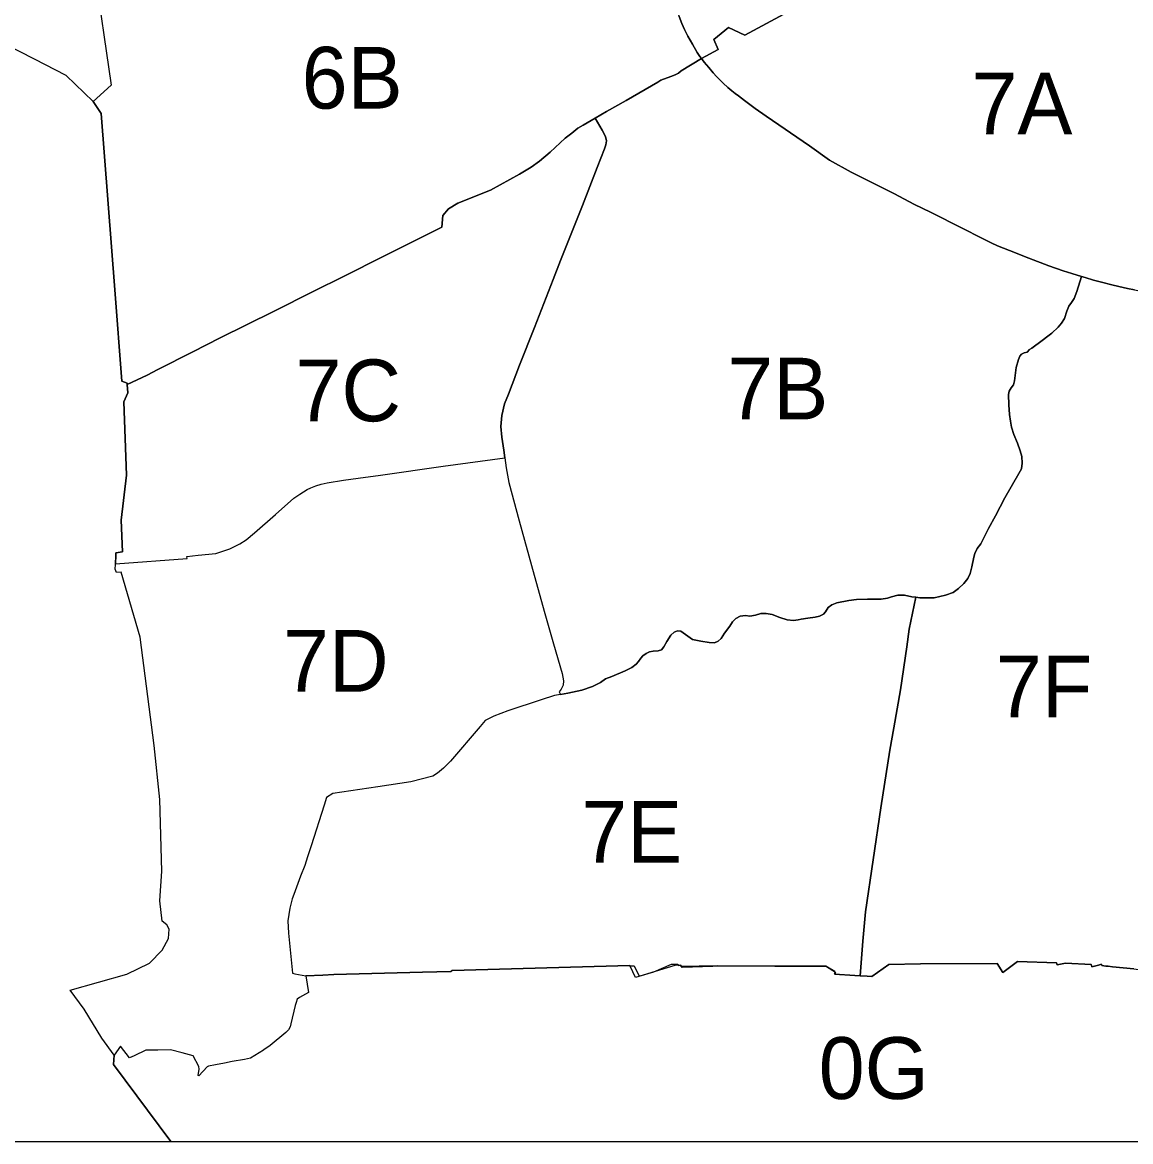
# Model space of a CAD drawing. Extents: x 152750 to 166250, y 378996 to 390000.
# Drawn here: x 157492 to 161080, y 379000 to 382624 of the extents above; entities that cross this region are included whole.
import ezdxf

# ---------------------------------------------------------------- set-up
doc = ezdxf.new("R2010")
doc.units = 0
doc.layers.add('BLT_Nummers', color=7, linetype='Continuous')
doc.layers.add('BLT_Shapes', color=7, linetype='Continuous')

msp = doc.modelspace()

# ---------------------------------------------------------------- linework, layer by layer
at = {"layer": 'BLT_Shapes'}
for p, q in [((159744.6, 382535.7), (159690.4, 382506.6)), ((159699.3, 382494.7), (159690.4, 382506.6)), ((159713.8, 382477.3), (159699.3, 382494.7)), ((159788.2, 382402.2), (159776.1, 382412.9)), ((159446.1, 382371), (159383.3, 382335)), ((159899.6, 382319.8), (159864.8, 382344.6)), ((159346.2, 382313.4), (159306.9, 382290.6)), ((159383.3, 382335), (159346.2, 382313.4)), ((159369, 382274.7), (159346.2, 382313.4)), ((160040.5, 382224.5), (159899.6, 382319.8)), ((159380.8, 382227.4), (159382.7, 382240.5)), ((159376.2, 382214.1), (159380.8, 382227.4)), ((160104.8, 382177.8), (160040.5, 382224.5)), ((160175.3, 382138.8), (160104.8, 382177.8)), ((160433.7, 382008.5), (160377.9, 382035.1)), ((160534, 381957.7), (160433.7, 382008.5)), ((158662.5, 381866.5), (158531.1, 381800.9)), ((160815.5, 381835.3), (160749.9, 381859.9)), ((160861.6, 381819.4), (160815.5, 381835.3)), ((158531.1, 381800.9), (158435.1, 381753.2)), ((160890, 381810.2), (160861.6, 381819.4)), ((160920.5, 381800.8), (160890, 381810.2)), ((160932.2, 381797.2), (160920.5, 381800.8)), ((161019.2, 381774.2), (160985.8, 381782.4)), ((159101.7, 381513.5), (159149.6, 381635.4)), ((160845, 381636.9), (160825.1, 381617.6)), ((160759.6, 381568.6), (160752.4, 381564.6)), ((159065.6, 381420.2), (159101.7, 381513.5)), ((160709.8, 381506.7), (160703.6, 381462.7)), ((157895.5, 381482), (157831.5, 381450.8)), ((157930.6, 381499.9), (157895.5, 381482)), ((157831.5, 381450.8), (157833.6, 381424.4)), ((160692.9, 381440), (160686.3, 381429.2)), ((160700.3, 381450.7), (160692.9, 381440)), ((160703.6, 381462.7), (160700.3, 381450.7)), ((157833.6, 381424.4), (157833.6, 381424.4)), ((159053.2, 381388.8), (159065.6, 381420.2)), ((160686.3, 381429.2), (160684.3, 381419.2)), ((160684.3, 381419.2), (160685.7, 381385.4)), ((160685.7, 381385.4), (160687.9, 381353.7)), ((160687.9, 381353.7), (160691.1, 381332.4)), ((160691.1, 381332.4), (160694.7, 381312.9)), ((159044.3, 381281), (159041.1, 381315.8)), ((159050.5, 381239), (159044.3, 381281)), ((159054, 381214.1), (159050.5, 381239)), ((160728.3, 381196.6), (160726.4, 381178.6)), ((160672.2, 381084.3), (160642.9, 381025.7)), ((157812.1, 381011.9), (157815.5, 380909)), ((160642.9, 381025.7), (160620.1, 380985.5)), ((160620.1, 380985.5), (160595.2, 380935.3)), ((160595.2, 380935.3), (160583.4, 380920.3)), ((157794.1, 380898.4), (157793, 380870.3)), ((157794.4, 380906), (157794.1, 380898.4)), ((157815.5, 380909), (157794.4, 380906)), ((160559.9, 380839.3), (160552.4, 380822.9)), ((160129.2, 380744.7), (160112.5, 380738.3)), ((160167.3, 380752), (160129.2, 380744.7)), ((160192.2, 380755.7), (160167.3, 380752)), ((160227.9, 380756.3), (160192.2, 380755.7)), ((160347.4, 380769.7), (160326.4, 380769.4)), ((160384.2, 380762.3), (160362.6, 380659)), ((160112.5, 380738.3), (160101.1, 380729.5)), ((159988.6, 380687.1), (159967.5, 380689.4)), ((159782, 380669.2), (159765.5, 380646.1)), ((159688.8, 380620.1), (159661.5, 380625.7)), ((159745, 380620.1), (159732.7, 380614.9)), ((159501, 380572.4), (159494.2, 380564.9)), ((159379.2, 380497.9), (159363.3, 380486.5)), ((159400, 380506.4), (159379.2, 380497.9)), ((159443.2, 380524.3), (159400, 380506.4)), ((160334.7, 380462.3), (160313.7, 380339.8)), ((159171.6, 380430.6), (159063.1, 380394.2)), ((159214.8, 380444.6), (159171.6, 380430.6)), ((159233.8, 380447.9), (159214.8, 380444.6)), ((159257.7, 380452.1), (159233.8, 380447.9)), ((159063.1, 380394.2), (159018.6, 380378)), ((160313.7, 380339.8), (160300.7, 380267.6)), ((160300.7, 380267.6), (160270.8, 380080.7)), ((158855.5, 380208.6), (158835.7, 380193)), ((158835.7, 380193), (158821.1, 380183.6)), ((158476.7, 380113.7), (158468.3, 380089.2)), ((158468.3, 380089.2), (158426.7, 379957.5)), ((160270.8, 380080.7), (160221.1, 379743.7)), ((160221.1, 379743.7), (160213.3, 379649.5)), ((160213.3, 379649.5), (160203.7, 379537.2)), ((158500, 379540.8), (158787.5, 379548.7)), ((158787.5, 379548.7), (158880.2, 379551.3)), ((159459.3, 379569.2), (159472.9, 379569.5)), ((159472.9, 379569.5), (159489, 379535.4)), ((159489, 379535.4), (159535.9, 379549.7)), ((160842.2, 379572.9), (160868.9, 379577.9)), ((160868.9, 379577.9), (160952.1, 379573.7)), ((160952.1, 379573.7), (160953.1, 379570.5)), ((160976.2, 379571.8), (160985.4, 379574.2)), ((161000.1, 379568.5), (161007.7, 379567.7)), ((161007.7, 379567.7), (161021.4, 379566.4)), ((158366, 379544.9), (158374.3, 379543.4)), ((158374.3, 379543.4), (158409.5, 379536.4)), ((160187.3, 379538.2), (160203.7, 379537.2)), ((160203.7, 379537.2), (160227.1, 379535.8))]:
    msp.add_line(p, q, dxfattribs=at)
for points in [[(157397.8, 383816.1), (157498.7, 383699.6), (157732.8, 383426.7), (157723.2, 383349.5), (157718.2, 383307.9), (157711.3, 383246), (157707.4, 383216.4), (157703.2, 383174.8), (157700.5, 383141.4), (157697.9, 383099.2), (157697.9, 383065.1), (157701.5, 382982.9), (157724.5, 382799.2), (157778.7, 382420.6), (157721.2, 382367.1), (157633.4, 382451.6), (157531.2, 382505), (157333.5, 382604.9)], [(157697.9, 383065.1), (157701.5, 382982.9), (157724.5, 382799.2), (157778.7, 382420.6), (157721.2, 382367.1)], [(159504.8, 382992), (159511, 382972.8), (159520.3, 382945.8), (159529.5, 382917.4), (159541.6, 382879), (159556.6, 382830.2), (159582.3, 382750.4), (159608.9, 382667.3), (159611, 382662.3), (159617.8, 382642.5), (159626.4, 382620.6), (159635.5, 382601.1), (159646.7, 382578.7), (159661.8, 382553.5), (159676.3, 382526.1), (159685.1, 382513.6), (159690.4, 382506.6)], [(160148.5, 382759.2), (160117.8, 382735.9), (160092.3, 382722), (159998.9, 382672.5), (159830.6, 382582), (159778.4, 382606.8), (159730.6, 382568.3), (159744.6, 382535.7)], [(159690.4, 382506.6), (159744.6, 382535.7), (159730.6, 382568.3), (159778.4, 382606.8), (159830.6, 382582), (159998.9, 382672.5)], [(159635.5, 382601.1), (159626.4, 382620.6), (159617.8, 382642.5)], [(155717.7, 379000), (157972.7, 379000), (157787.3, 379250.2), (157788.7, 379279.4), (157749, 379335.4), (157691.9, 379428.3), (157646.2, 379490.7), (157830.3, 379542), (157903.5, 379577.9), (157944.1, 379620.1), (157965.1, 379658), (157967.3, 379687.8), (157959.6, 379702), (157944.4, 379713.7), (157937.2, 379779.1), (157943.6, 379875.6), (157936.4, 380107.4), (157918.8, 380283), (157872.7, 380633.2), (157811.6, 380843.6), (157796.6, 380842.1), (157792.4, 380853.5), (157793, 380868), (157794.1, 380898.4), (157794.4, 380906), (157815.5, 380909), (157812.1, 381011.9), (157828.6, 381158), (157820.6, 381395.1), (157833.6, 381424.4), (157831.5, 381450.8), (157831.1, 381455.5), (157813.9, 381461.8), (157791.1, 381758.1), (157746.8, 382329.2), (157721.2, 382367.1), (157633.4, 382451.6), (157531.2, 382505), (157333.5, 382604.9)], [(159676.3, 382526.1), (159661.8, 382553.5), (159646.7, 382578.7), (159635.5, 382601.1)], [(159690.4, 382506.6), (159685.1, 382513.6), (159676.3, 382526.1)], [(159346.2, 382313.4), (159383.3, 382335), (159446.1, 382371), (159548.6, 382430.3), (159559.2, 382436.5), (159591.1, 382448.3), (159605.5, 382454.2), (159615.9, 382459.3), (159624.4, 382466.4), (159690.4, 382506.6)], [(159690.4, 382506.6), (159624.4, 382466.4), (159615.9, 382459.3), (159605.5, 382454.2)], [(159690.4, 382506.6), (159699.3, 382494.7), (159713.8, 382477.3), (159728.3, 382460.4), (159739.5, 382448), (159748.4, 382438.3), (159760.8, 382427), (159776.1, 382412.9), (159788.2, 382402.2), (159799.8, 382393.1), (159810.1, 382385.4), (159829.9, 382370.3), (159864.8, 382344.6), (159899.6, 382319.8), (160040.5, 382224.5), (160104.8, 382177.8), (160175.3, 382138.8), (160314.9, 382068.2), (160377.9, 382035.1), (160433.7, 382008.5), (160534, 381957.7), (160598.4, 381924.9), (160628.2, 381910.4), (160648.6, 381900.4), (160687.6, 381885.3), (160749.9, 381859.9), (160815.5, 381835.3), (160861.6, 381819.4), (160890, 381810.2), (160920.5, 381800.8)], [(159605.5, 382454.2), (159591.1, 382448.3), (159559.2, 382436.5)], [(159776.1, 382412.9), (159760.8, 382427), (159748.4, 382438.3), (159739.5, 382448), (159728.3, 382460.4), (159713.8, 382477.3)], [(159559.2, 382436.5), (159548.6, 382430.3), (159446.1, 382371)], [(159810.1, 382385.4), (159799.8, 382393.1), (159788.2, 382402.2)], [(159864.8, 382344.6), (159829.9, 382370.3), (159810.1, 382385.4)], [(157721.2, 382367.1), (157746.8, 382329.2), (157791.1, 381758.1)], [(157831.5, 381450.8), (157895.5, 381482), (157930.6, 381499.9), (158043.1, 381557.2), (158132.4, 381602.5), (158304.5, 381688.1), (158435.1, 381753.2), (158531.1, 381800.9), (158662.5, 381866.5), (158849.6, 381960.9), (158852.7, 381998.3), (158870.9, 382020.4), (158901.8, 382038.4), (159007.7, 382081), (159100.8, 382132.2), (159139.2, 382155.4), (159165.5, 382174.1), (159200.4, 382203.9), (159249.6, 382248.4), (159270.8, 382265.2), (159290.5, 382281.1), (159306.9, 382290.6), (159346.2, 382313.4)], [(159346.2, 382313.4), (159369, 382274.7), (159380.1, 382253.8), (159382.7, 382240.5), (159380.8, 382227.4), (159376.2, 382214.1), (159352.7, 382153.5), (159304.8, 382030.6), (159234.4, 381852.5), (159210.6, 381791.3), (159149.6, 381635.4), (159101.7, 381513.5), (159065.6, 381420.2), (159053.2, 381388.8), (159044, 381351), (159041.1, 381315.8), (159044.3, 381281), (159050.5, 381239), (159054, 381214.1)], [(159306.9, 382290.6), (159290.5, 382281.1), (159270.8, 382265.2), (159249.6, 382248.4), (159200.4, 382203.9)], [(159382.7, 382240.5), (159380.1, 382253.8), (159369, 382274.7)], [(159200.4, 382203.9), (159165.5, 382174.1), (159139.2, 382155.4), (159100.8, 382132.2), (159007.7, 382081), (158901.8, 382038.4), (158870.9, 382020.4), (158852.7, 381998.3), (158849.6, 381960.9), (158662.5, 381866.5)], [(159234.4, 381852.5), (159304.8, 382030.6), (159352.7, 382153.5), (159376.2, 382214.1)], [(160377.9, 382035.1), (160314.9, 382068.2), (160175.3, 382138.8)], [(160749.9, 381859.9), (160687.6, 381885.3), (160648.6, 381900.4), (160628.2, 381910.4), (160598.4, 381924.9), (160534, 381957.7)], [(159149.6, 381635.4), (159210.6, 381791.3), (159234.4, 381852.5)], [(160384.2, 380762.3), (160397.2, 380760.4), (160443.7, 380760.4), (160480.7, 380769.5), (160505, 380778.3), (160523.1, 380790.5), (160539.8, 380807), (160552.4, 380822.9), (160559.9, 380839.3), (160565.9, 380860.8), (160571.9, 380891.8), (160575.3, 380904.6), (160583.4, 380920.3), (160595.2, 380935.3), (160620.1, 380985.5), (160642.9, 381025.7), (160672.2, 381084.3), (160718, 381163), (160726.4, 381178.6), (160728.3, 381196.6), (160727.9, 381217.9), (160722.6, 381236.2), (160713.2, 381261.7), (160701.5, 381289.6), (160694.7, 381312.9), (160691.1, 381332.4), (160687.9, 381353.7), (160685.7, 381385.4), (160684.3, 381419.2), (160686.3, 381429.2), (160692.9, 381440), (160700.3, 381450.7), (160703.6, 381462.7), (160709.8, 381506.7), (160717.2, 381532.4), (160721.4, 381543.1), (160726.1, 381549.5), (160734.9, 381553.5), (160745.1, 381556.1), (160752.4, 381564.6), (160759.6, 381568.6), (160793.2, 381594.1), (160811.5, 381607.3), (160825.1, 381617.6), (160845, 381636.9), (160856.3, 381649.5), (160865.3, 381665), (160873.1, 381688.5), (160879.4, 381705.4), (160888.2, 381716.6), (160896.9, 381729.5), (160905.8, 381752.3), (160920.5, 381800.8)], [(160920.5, 381800.8), (160905.8, 381752.3), (160896.9, 381729.5), (160888.2, 381716.6)], [(160920.5, 381800.8), (160932.2, 381797.2), (160959.8, 381789.2), (160985.8, 381782.4), (161019.2, 381774.2), (161041.4, 381768.8), (161069.7, 381762.6), (161092.3, 381757.9), (161123.3, 381751.7), (161157.6, 381746.1), (161183, 381741.6), (161215.2, 381736.9), (161252.7, 381731.9), (161261.7, 381730.7)], [(160985.8, 381782.4), (160959.8, 381789.2), (160932.2, 381797.2)], [(161092.3, 381757.9), (161069.7, 381762.6), (161041.4, 381768.8), (161019.2, 381774.2)], [(157791.1, 381758.1), (157813.9, 381461.8), (157831.1, 381455.5), (157831.5, 381450.8)], [(158435.1, 381753.2), (158304.5, 381688.1), (158132.4, 381602.5)], [(160888.2, 381716.6), (160879.4, 381705.4), (160873.1, 381688.5), (160865.3, 381665)], [(160865.3, 381665), (160856.3, 381649.5), (160845, 381636.9)], [(160825.1, 381617.6), (160811.5, 381607.3), (160793.2, 381594.1), (160759.6, 381568.6)], [(158132.4, 381602.5), (158043.1, 381557.2), (157930.6, 381499.9)], [(160721.4, 381543.1), (160717.2, 381532.4), (160709.8, 381506.7)], [(160752.4, 381564.6), (160745.1, 381556.1), (160734.9, 381553.5), (160726.1, 381549.5), (160721.4, 381543.1)], [(157833.6, 381424.4), (157820.6, 381395.1), (157828.6, 381158), (157812.1, 381011.9)], [(159041.1, 381315.8), (159044, 381351), (159053.2, 381388.8)], [(160694.7, 381312.9), (160701.5, 381289.6), (160713.2, 381261.7), (160722.6, 381236.2), (160727.9, 381217.9), (160728.3, 381196.6)], [(157793, 380870.3), (158025.2, 380887.5), (158024.6, 380894.9), (158061.3, 380898.2), (158117.6, 380904.4), (158163.6, 380919), (158196.3, 380935.3), (158215.8, 380948), (158242.8, 380971), (158311.6, 381030.8), (158371.1, 381082.8), (158389.8, 381096.6), (158414.1, 381111.2), (158426, 381116.6), (158442, 381123.1), (158459.3, 381128.6), (158478.2, 381133.4), (158531.3, 381141.5), (158579.2, 381147.5), (158651.4, 381157.8), (158853.8, 381186.5), (159054, 381214.1)], [(159054, 381214.1), (159058.5, 381181.6), (159066.3, 381134.5), (159100.4, 381010.3), (159149.1, 380833.8), (159183.6, 380709.5), (159211.2, 380612), (159239.5, 380515.5), (159244.1, 380491.4), (159243.1, 380477.8), (159236.6, 380465.4), (159230.1, 380456), (159233.8, 380447.9)], [(160726.4, 381178.6), (160718, 381163), (160672.2, 381084.3)], [(160583.4, 380920.3), (160575.3, 380904.6), (160571.9, 380891.8), (160565.9, 380860.8), (160559.9, 380839.3)], [(160552.4, 380822.9), (160539.8, 380807), (160523.1, 380790.5), (160505, 380778.3), (160480.7, 380769.5), (160443.7, 380760.4), (160397.2, 380760.4), (160384.2, 380762.3)], [(159233.8, 380447.9), (159257.7, 380452.1), (159303.2, 380461.2), (159337.9, 380473.9), (159363.3, 380486.5), (159379.2, 380497.9), (159400, 380506.4), (159443.2, 380524.3), (159465.3, 380535.3), (159479.3, 380545.7), (159486.1, 380554.2), (159494.2, 380564.9), (159501, 380572.4), (159511.1, 380580.8), (159522.1, 380585.7), (159534.2, 380587.6), (159550.7, 380589.3), (159560.5, 380592.2), (159568.9, 380601.6), (159578.7, 380619.5), (159591, 380640), (159602.1, 380649.4), (159612.8, 380653.6), (159623.2, 380652.3), (159638.8, 380641.9), (159661.5, 380625.7), (159688.8, 380620.1), (159714.8, 380615.9), (159732.7, 380614.9), (159745, 380620.1), (159753.8, 380629.2), (159765.5, 380646.1), (159782, 380669.2), (159790.8, 380682.5), (159801.5, 380693.9), (159815.5, 380701.4), (159832.7, 380703.3), (159847, 380701.7), (159865.5, 380705), (159882.1, 380709.5), (159900, 380710.2), (159918.8, 380706.3), (159944.5, 380696.5), (159967.5, 380689.4), (159988.6, 380687.1), (160003.3, 380689.5), (160013.6, 380691), (160035.2, 380695.3), (160058.4, 380698.1), (160072.5, 380701.5), (160085.6, 380707.3), (160092, 380715.5), (160101.1, 380729.5), (160112.5, 380738.3), (160129.2, 380744.7), (160167.3, 380752), (160192.2, 380755.7), (160227.9, 380756.3), (160254.8, 380756.1), (160271.8, 380756.4), (160293.2, 380759.4), (160306.1, 380763.9), (160326.4, 380769.4), (160347.4, 380769.7), (160371.7, 380764.1), (160384.2, 380762.3)], [(160203.7, 379537.2), (160213.3, 379649.5), (160221.1, 379743.7), (160270.8, 380080.7), (160300.7, 380267.6), (160313.7, 380339.8), (160334.7, 380462.3), (160355.7, 380601.6), (160362.6, 380659), (160384.2, 380762.3)], [(160293.2, 380759.4), (160271.8, 380756.4), (160254.8, 380756.1), (160227.9, 380756.3)], [(160326.4, 380769.4), (160306.1, 380763.9), (160293.2, 380759.4)], [(160384.2, 380762.3), (160371.7, 380764.1), (160347.4, 380769.7)], [(159918.8, 380706.3), (159900, 380710.2), (159882.1, 380709.5), (159865.5, 380705), (159847, 380701.7), (159832.7, 380703.3)], [(160101.1, 380729.5), (160092, 380715.5), (160085.6, 380707.3), (160072.5, 380701.5)], [(159832.7, 380703.3), (159815.5, 380701.4), (159801.5, 380693.9), (159790.8, 380682.5), (159782, 380669.2)], [(159967.5, 380689.4), (159944.5, 380696.5), (159918.8, 380706.3)], [(160013.6, 380691), (160003.3, 380689.5), (159988.6, 380687.1)], [(160072.5, 380701.5), (160058.4, 380698.1), (160035.2, 380695.3), (160013.6, 380691)], [(159661.5, 380625.7), (159638.8, 380641.9), (159623.2, 380652.3), (159612.8, 380653.6), (159602.1, 380649.4), (159591, 380640), (159578.7, 380619.5), (159568.9, 380601.6), (159560.5, 380592.2), (159550.7, 380589.3), (159534.2, 380587.6)], [(159765.5, 380646.1), (159753.8, 380629.2), (159745, 380620.1)], [(160362.6, 380659), (160355.7, 380601.6), (160334.7, 380462.3)], [(159732.7, 380614.9), (159714.8, 380615.9), (159688.8, 380620.1)], [(159494.2, 380564.9), (159486.1, 380554.2), (159479.3, 380545.7), (159465.3, 380535.3), (159443.2, 380524.3)], [(159534.2, 380587.6), (159522.1, 380585.7), (159511.1, 380580.8), (159501, 380572.4)], [(159363.3, 380486.5), (159337.9, 380473.9), (159303.2, 380461.2), (159257.7, 380452.1)], [(159018.6, 380378), (158990.3, 380363), (158973.4, 380344.5)], [(158973.4, 380344.5), (158877.9, 380232.1), (158855.5, 380208.6)], [(158821.1, 380183.6), (158749.9, 380165.1), (158642.4, 380149.2)], [(158642.4, 380149.2), (158496.9, 380127.4), (158476.7, 380113.7)], [(158426.7, 379957.5), (158415.1, 379921.6), (158405.9, 379893.9), (158392, 379859.2)], [(158392, 379859.2), (158370.1, 379800.3), (158365.3, 379786.1)], [(158365.3, 379786.1), (158357.5, 379755.6), (158351, 379714.6), (158353.6, 379674.9)], [(158353.6, 379674.9), (158356.2, 379642.4), (158366, 379544.9)], [(161090.1, 379559.8), (161021.4, 379566.4), (161007.7, 379567.7), (161000.1, 379568.5), (160992.7, 379569.2), (160987, 379569.8), (160985.4, 379574.2), (160976.2, 379571.8), (160954.5, 379566.2), (160953.1, 379570.5), (160952.1, 379573.7), (160868.9, 379577.9), (160842.2, 379572.9), (160840.2, 379579.1), (160714, 379582.7), (160665.8, 379547.5), (160647.9, 379576.3), (160400, 379575.7), (160296.9, 379573.4), (160242.2, 379534.9), (160227.1, 379535.8), (160203.7, 379537.2), (160187.3, 379538.2), (160121.5, 379542.3), (160124.1, 379547.3), (160095.5, 379565.4), (159761.1, 379568.1), (159627.9, 379563.8), (159622.8, 379570.9), (159604.1, 379570.6), (159476.5, 379531.5), (159459.8, 379567.9), (159458.7, 379570.5), (158883, 379553.7), (158880.4, 379551.5), (158880.2, 379551.3), (158787.5, 379548.7), (158500, 379540.8), (158464.2, 379539.1), (158409.5, 379536.4), (158417.9, 379482.4), (158388.5, 379466.4), (158381.5, 379461.5), (158378.1, 379450.9), (158374.6, 379440.3), (158361.2, 379380.9), (158359.2, 379372), (158353.1, 379361.5), (158344.6, 379352.9), (158294.5, 379311.5), (158273.3, 379297), (158271.9, 379296), (158229.8, 379270.7), (158210.6, 379265.6), (158171.5, 379259.9), (158146, 379253.7), (158116.9, 379249.1), (158094, 379244.8), (158089.7, 379242.3), (158063.2, 379212.5), (158061.3, 379214.3), (158064.4, 379234.1), (158063.2, 379243.5), (158044.5, 379278), (158008.6, 379287.3), (157971.7, 379296.8), (157930.2, 379296.2), (157891.5, 379295.7), (157853.6, 379278), (157838.5, 379271.3), (157809.9, 379309.3), (157788.7, 379279.4), (157787.3, 379250.2), (157972.7, 379000), (163144.2, 379000)], [(158880.2, 379551.3), (158880.4, 379551.5), (158883, 379553.7)], [(158883, 379553.7), (159458.7, 379570.5), (159459.3, 379569.2)], [(159535.9, 379549.7), (159593.3, 379574.1), (159613.6, 379574.2), (159615.2, 379570.7)], [(159615.2, 379570.7), (159622.8, 379570.9), (159625.1, 379567.7)], [(159625.1, 379567.7), (159741.3, 379570.6), (160093.5, 379569.5), (160121.7, 379552.3), (160120.5, 379549.6)], [(160120.5, 379549.6), (160124.1, 379547.3), (160121.5, 379542.3), (160187.3, 379538.2)], [(160227.1, 379535.8), (160242.2, 379534.9), (160296.9, 379573.4)], [(160296.9, 379573.4), (160400, 379575.7), (160647.9, 379576.3), (160665.8, 379547.5), (160714, 379582.7)], [(160714, 379582.7), (160840.2, 379579.1), (160842.2, 379572.9)], [(160953.1, 379570.5), (160954.5, 379566.2), (160976.2, 379571.8)], [(160985.4, 379574.2), (160987, 379569.8), (160992.7, 379569.2), (161000.1, 379568.5)], [(161021.4, 379566.4), (161090.1, 379559.8), (161204.6, 379542)], [(158409.5, 379536.4), (158464.2, 379539.1), (158500, 379540.8)]]:
    msp.add_lwpolyline(points, dxfattribs=at)
msp.add_lwpolyline([(157872.7, 380633.2), (157811.6, 380843.6), (157796.6, 380842.1), (157792.4, 380853.5), (157793, 380868), (157793, 380870.3), (158025.2, 380887.5), (158024.6, 380894.9), (158061.3, 380898.2), (158117.6, 380904.4), (158163.6, 380919), (158196.3, 380935.3), (158215.8, 380948), (158242.8, 380971), (158311.6, 381030.8), (158371.1, 381082.8), (158389.8, 381096.6), (158414.1, 381111.2), (158426, 381116.6), (158442, 381123.1), (158459.3, 381128.6), (158478.2, 381133.4), (158531.3, 381141.5), (158579.2, 381147.5), (158651.4, 381157.8), (158853.8, 381186.5), (159054, 381214.1), (159058.5, 381181.6), (159066.3, 381134.5), (159100.4, 381010.3), (159149.1, 380833.8), (159183.6, 380709.5), (159211.2, 380612), (159239.5, 380515.5), (159244.1, 380491.4), (159243.1, 380477.8), (159236.6, 380465.4), (159230.1, 380456), (159233.8, 380447.9), (159214.8, 380444.6), (159171.6, 380430.6), (159063.1, 380394.2), (159018.6, 380378), (158990.3, 380363), (158973.4, 380344.5), (158877.9, 380232.1), (158855.5, 380208.6), (158835.7, 380193), (158821.1, 380183.6), (158749.9, 380165.1), (158642.4, 380149.2), (158496.9, 380127.4), (158476.7, 380113.7), (158468.3, 380089.2), (158426.7, 379957.5), (158415.1, 379921.6), (158405.9, 379893.9), (158392, 379859.2), (158370.1, 379800.3), (158365.3, 379786.1), (158357.5, 379755.6), (158351, 379714.6), (158353.6, 379674.9), (158356.2, 379642.4), (158366, 379544.9), (158374.3, 379543.4), (158409.5, 379536.4), (158417.9, 379482.4), (158388.5, 379466.4), (158381.5, 379461.5), (158378.1, 379450.9), (158374.6, 379440.3), (158361.2, 379380.9), (158359.2, 379372), (158353.1, 379361.5), (158344.6, 379352.9), (158294.5, 379311.5), (158273.3, 379297), (158271.9, 379296), (158229.8, 379270.7), (158210.6, 379265.6), (158171.5, 379259.9), (158146, 379253.7), (158116.9, 379249.1), (158094, 379244.8), (158089.7, 379242.3), (158063.2, 379212.5), (158061.3, 379214.3), (158064.4, 379234.1), (158063.2, 379243.5), (158044.5, 379278), (158008.6, 379287.3), (157971.7, 379296.8), (157930.2, 379296.2), (157891.5, 379295.7), (157853.6, 379278), (157838.5, 379271.3), (157809.9, 379309.3), (157788.7, 379279.4), (157749, 379335.4), (157691.9, 379428.3), (157646.2, 379490.7), (157830.3, 379542), (157903.5, 379577.9), (157944.1, 379620.1), (157965.1, 379658), (157967.3, 379687.8), (157959.6, 379702), (157944.4, 379713.7), (157937.2, 379779.1), (157943.6, 379875.6), (157936.4, 380107.4), (157918.8, 380283)], close=True, dxfattribs=at)

# ---------------------------------------------------------------- texts
at = {"layer": 'BLT_Nummers'}
for s, p in [('6B', (158395.9, 382344.5)), ('7A', (160564.4, 382261.2)), ('7C', (158375.8, 381332.1)), ('7B', (159774, 381338)), ('7D', (158335.7, 380456.6)), ('7F', (160643.7, 380373.2)), ('7E', (159301.3, 379902.7)), ('0G', (160070, 379138.1))]:
    msp.add_text(s, height=200, dxfattribs=at).set_placement(p)

doc.saveas('drawing.dxf')
